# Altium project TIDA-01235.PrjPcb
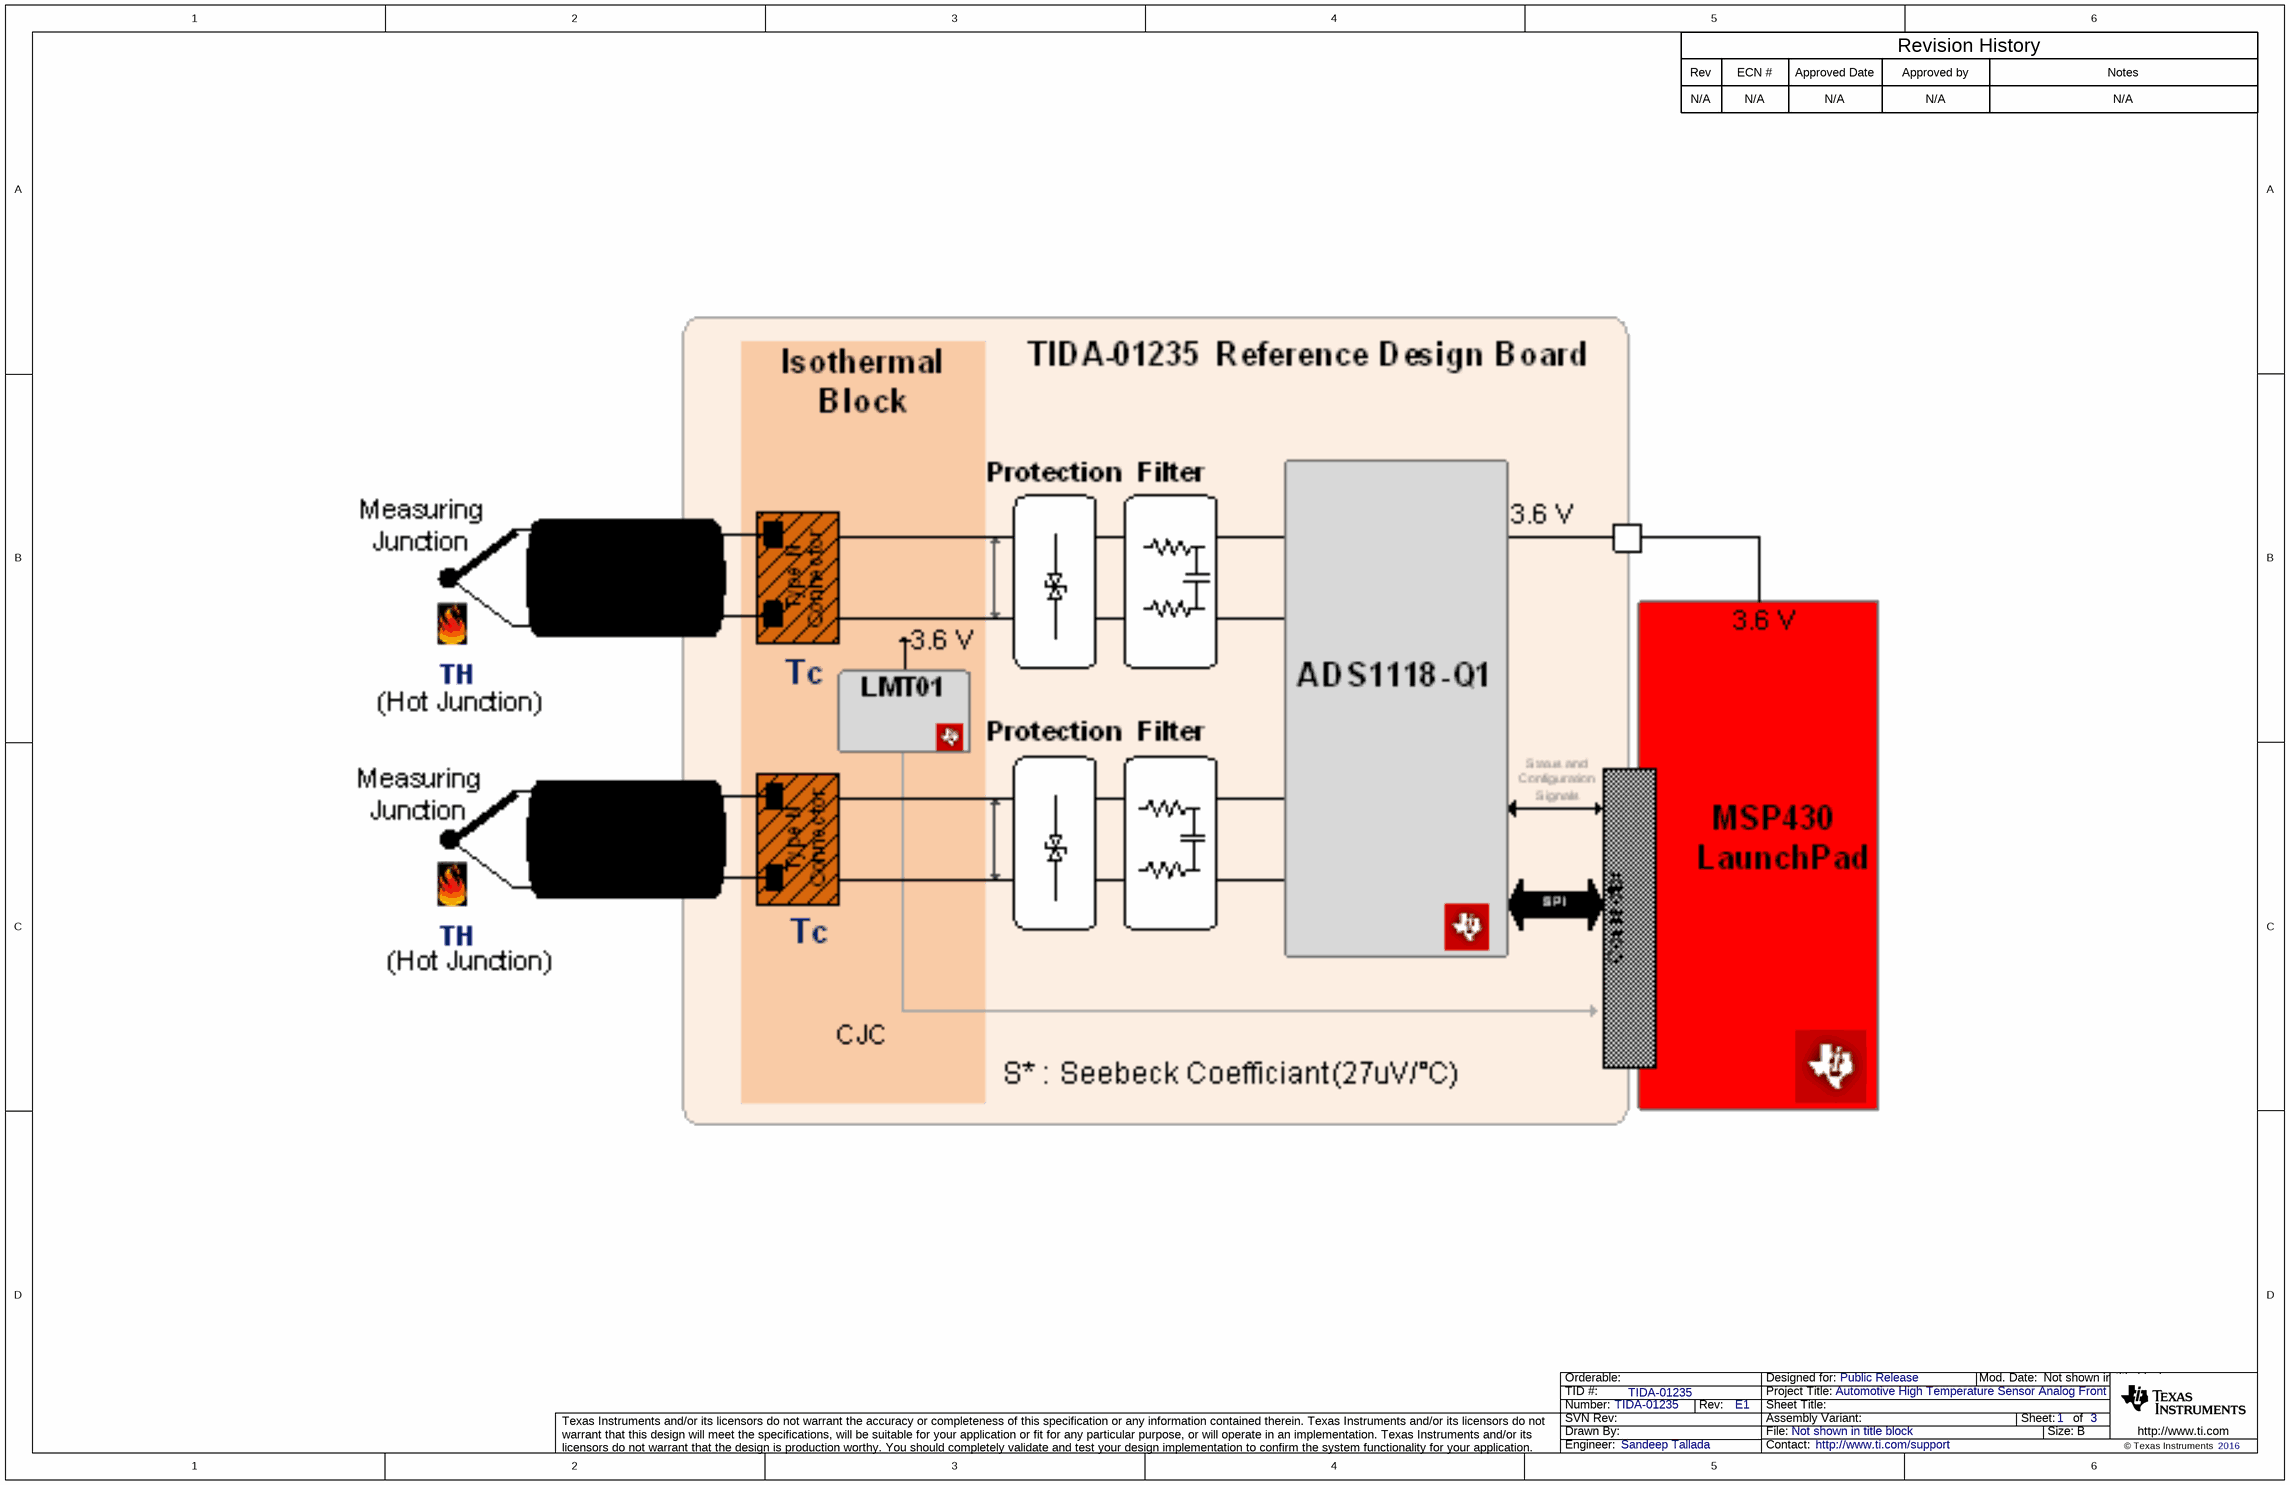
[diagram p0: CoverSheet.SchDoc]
CopyrightYear: 2016; PCB_Layout: Sandeep Tallada; PCB_Rev: E1; PRJ_Customer: Public Release; PRJ_Engineer: Sandeep Tallada; PRJ_Number: TIDA-01235; PRJ_Title: Automotive High Temperature Sensor Analog Front End Reference Design; SCH_Rev: E1; TechSupport: http://www.ti.com/support; TID: TIDA-01235
3 sheets, 60 parts. Net scope: flat (ports and power ports of the same name join across sheets).
Board file: PCB.PcbDoc
Sheets:
  CoverSheet.SchDoc
  BlankSheet.SchDoc
  EVM_Hardware.SchDoc

## Sheet CoverSheet.SchDoc
size 431 x 279 mm; Date: Not shown in title block; ApprovedBy: Not shown in title block; CheckedBy: Not shown in title block; Author: Not shown in title block; CompanyName: Not shown in title block; Engineer: Not shown in title block; Organization: Not shown in title block; Address1: Not shown in title block; Address2: Not shown in title block; Address3: Not shown in title block; Address4: Not shown in title block; DocumentNumber: 1; Revision: Use project parameter SCH_Rev; SheetNumber: 1; SheetTotal: 3; PageSetup: Record=PageOptions¦CenterHorizontal=True¦CenterVertical=True¦PrintScale=1.00¦XCorrection=1.00¦YCorrection=1.00¦PrintKind=0¦BorderSize=5000000¦LeftOffset=0¦BottomOffset=0¦Orientation=2¦PaperLength=1000¦PaperWidth=1000¦Scale=100¦PaperSource=15¦PrintQuality=600¦MediaType=1¦DitherType=10¦PaperKind=Letter¦PrintScaleMode=1

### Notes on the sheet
- Rev
- N/A
- ECN #
- Approved Date
- Approved by
- Revision History
- Notes
- Place Block Diagram here (if appropriate) or delete this text box.
  If using a block diagram from another tool, save the picture as a .bmp file.
  Then, use menu Place|Drawing Tools|Graphic to insert the .png/.svg/.bmp file on the schematic.

## Sheet BlankSheet.SchDoc: Automotive HTS Schematic
size 431 x 279 mm; Date: Not shown in title block; ApprovedBy: Not shown in title block; CheckedBy: Not shown in title block; Author: Not shown in title block; CompanyName: Not shown in title block; DrawnBy: Sandeep Tallada; Engineer: Not shown in title block; Organization: Not shown in title block; Address1: Not shown in title block; Address2: Not shown in title block; Address3: Not shown in title block; Address4: Not shown in title block; DocumentNumber: 1; Revision: Use project parameter SCH_Rev; SheetNumber: 1; SheetTotal: 1; PageSetup: Record=PageOptions¦CenterHorizontal=True¦CenterVertical=True¦PrintScale=1.00¦XCorrection=1.00¦YCorrection=1.00¦PrintKind=0¦BorderSize=5000000¦LeftOffset=0¦BottomOffset=0¦Orientation=2¦PaperLength=1000¦PaperWidth=1000¦Scale=100¦PaperSource=15¦PrintQuality=600¦MediaType=1¦DitherType=10¦PaperKind=Letter¦PrintScaleMode=1
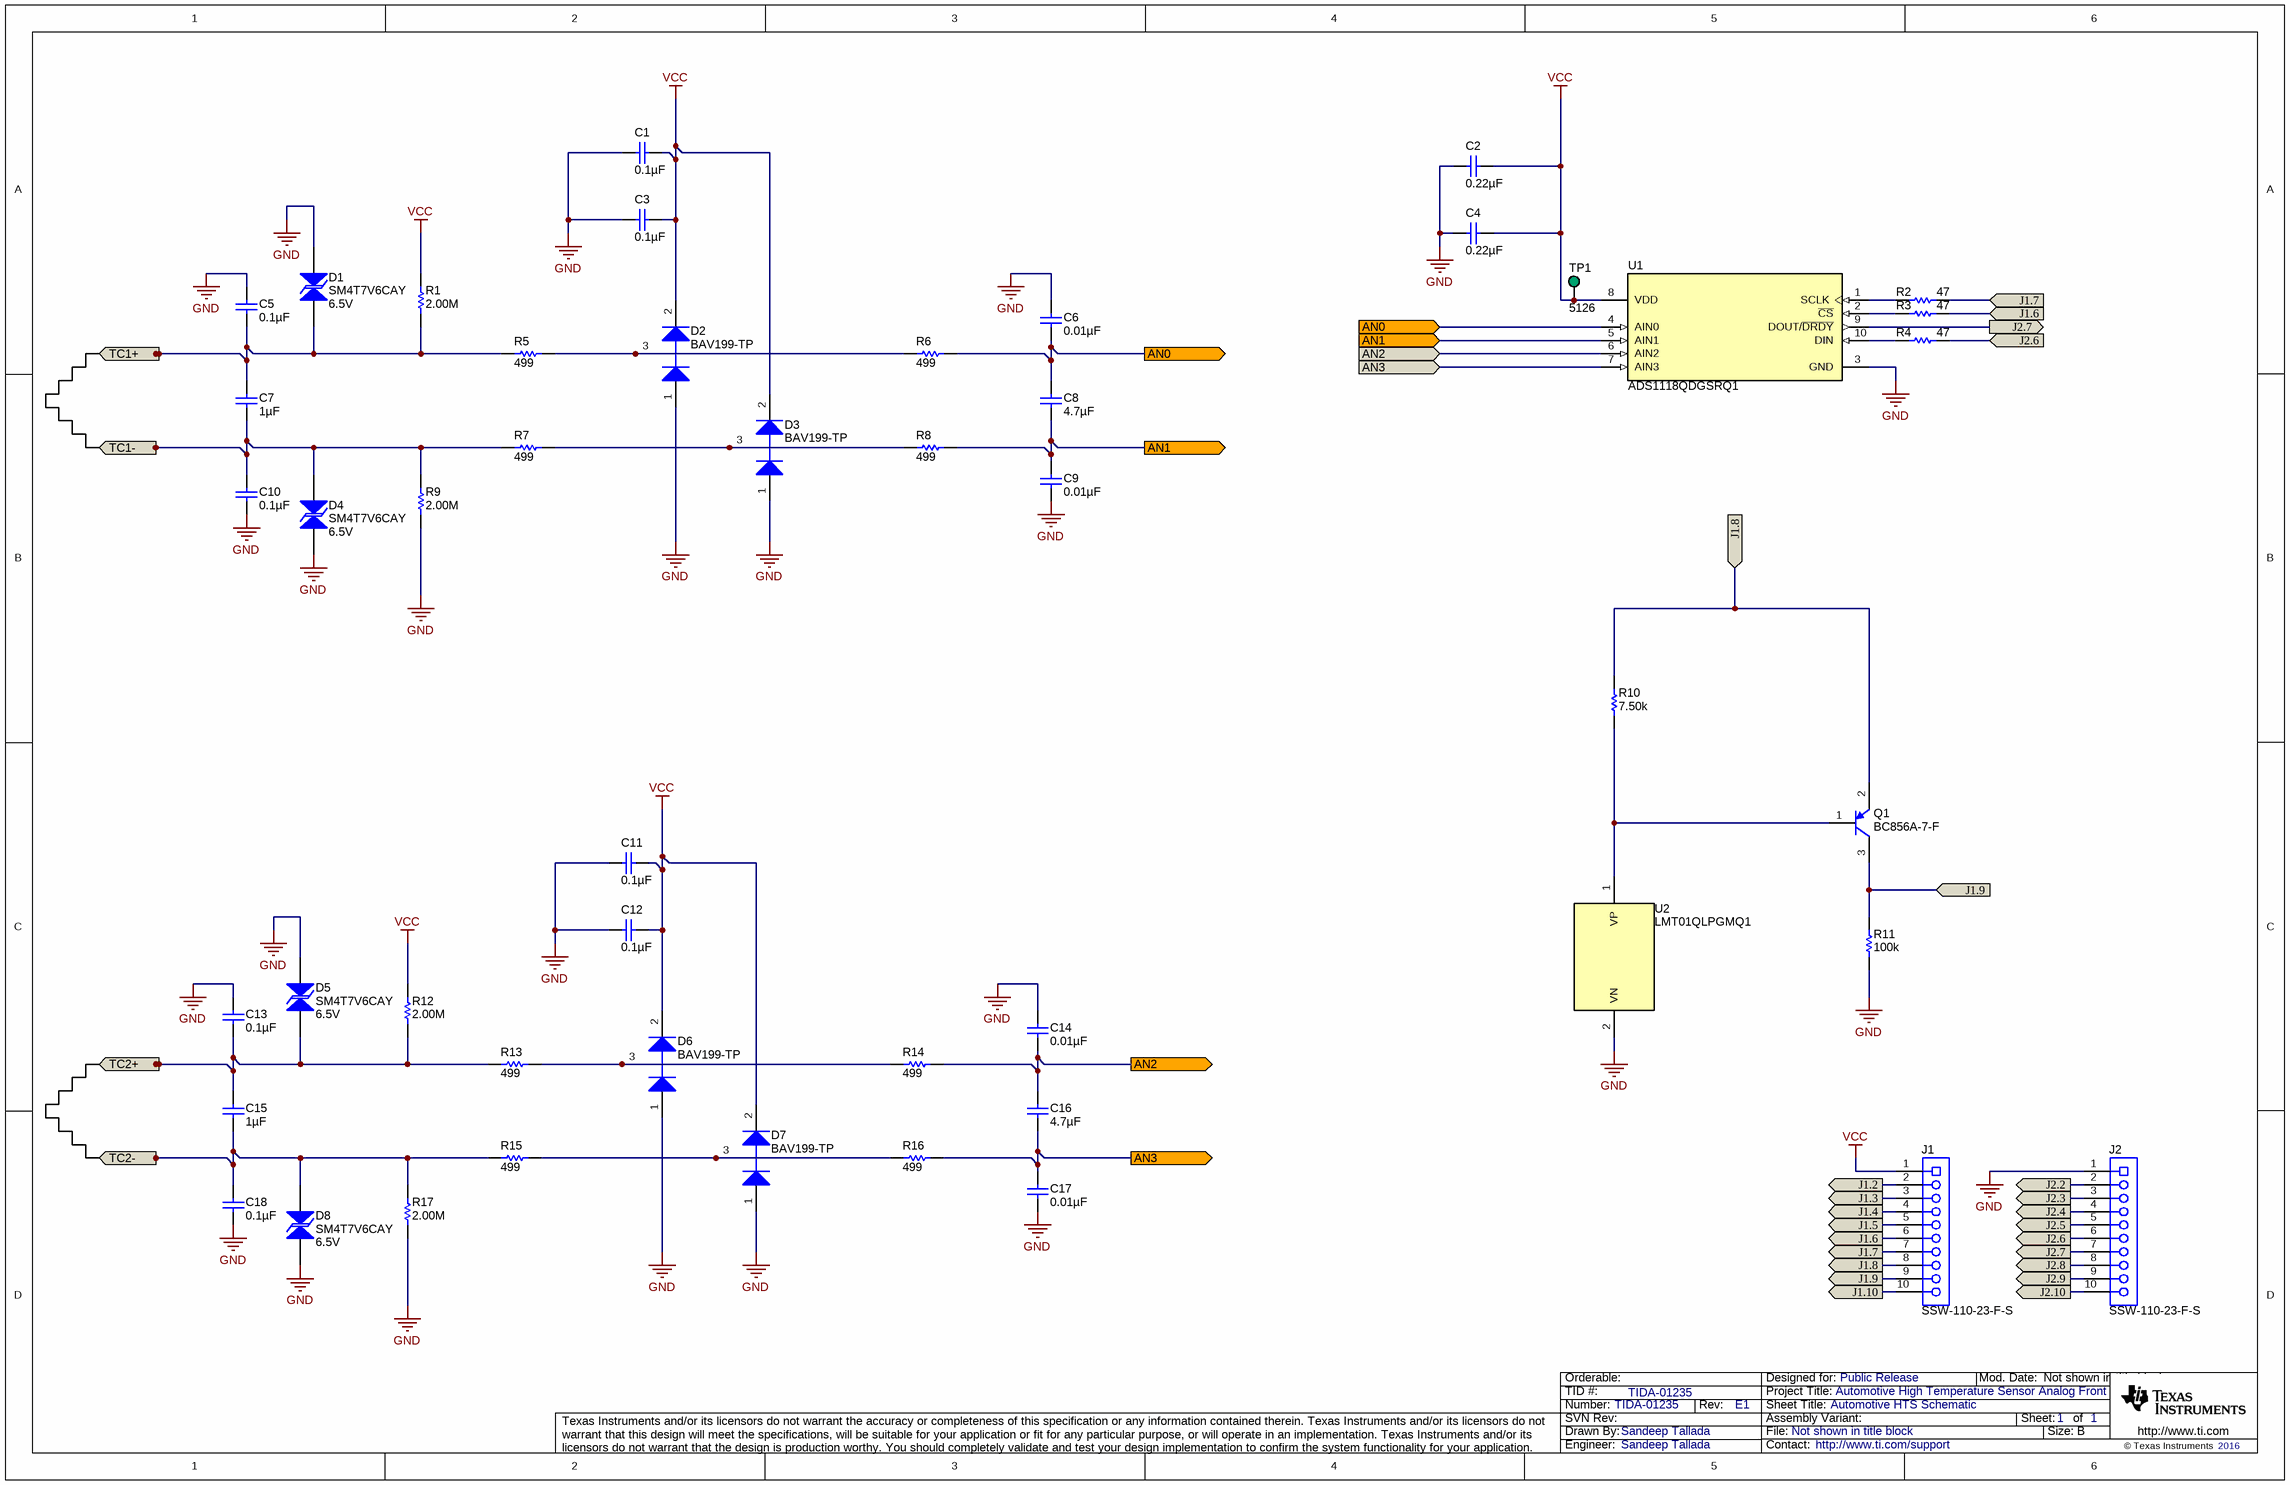
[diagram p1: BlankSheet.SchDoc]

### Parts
C1  ValueDisplayed: 0.1µF  [0805]  (hidden comment: CGA4J2X8R1H104M125AA)
C2  ValueDisplayed: 0.22µF  [0603S]  (hidden comment: CGA3E3X8R1E224K080AB)
C3  ValueDisplayed: 0.1µF  [0805]  (hidden comment: CGA4J2X8R1H104M125AA)
C4  ValueDisplayed: 0.22µF  [0603S]  (hidden comment: CGA3E3X8R1E224K080AB)
C5  ValueDisplayed: 0.1µF  [0805]  (hidden comment: CGA4J2X8R1H104M125AA)
C6  ValueDisplayed: 0.01µF  [0603S]  (hidden comment: C1608NP01H103J080AA)
C7  ValueDisplayed: 1µF  [1206_180]  (hidden comment: CGA5L3X8R1H105K160AB)
C8  ValueDisplayed: 4.7µF  [0603S]  (hidden comment: C0603C475K8PACTU)
C9  ValueDisplayed: 0.01µF  [0603S]  (hidden comment: C1608NP01H103J080AA)
C10  ValueDisplayed: 0.1µF  [0805]  (hidden comment: CGA4J2X8R1H104M125AA)
C11  ValueDisplayed: 0.1µF  [0805_HV]  (hidden comment: CGA4J2X8R1H104M125AA)
C12  ValueDisplayed: 0.1µF  [0805_HV]  (hidden comment: CGA4J2X8R1H104M125AA)
C13  ValueDisplayed: 0.1µF  [0805]  (hidden comment: CGA4J2X8R1H104M125AA)
C14  ValueDisplayed: 0.01µF  [0603S]  (hidden comment: C1608NP01H103J080AA)
C15  ValueDisplayed: 1µF  [1206_180]  (hidden comment: CGA5L3X8R1H105K160AB)
C16  ValueDisplayed: 4.7µF  [0603S]  (hidden comment: C0603C475K8PACTU)
C17  ValueDisplayed: 0.01µF  [0603S]  (hidden comment: C1608NP01H103J080AA)
C18  ValueDisplayed: 0.1µF  [0805]  (hidden comment: CGA4J2X8R1H104M125AA)
D1  SM4T7V6CAY  value 6.5V  [SMA]
D2  BAV199-TP  [SOT-23]
D3  BAV199-TP  [SOT-23]
D4  SM4T7V6CAY  value 6.5V  [SMA]
D5  SM4T7V6CAY  value 6.5V  [SMA]
D6  BAV199-TP  [SOT-23]
D7  BAV199-TP  [SOT-23]
D8  SM4T7V6CAY  value 6.5V  [SMA]
J1  SSW-110-23-F-S  [CONN_SSW-110-23-F-S]
J2  SSW-110-23-F-S  [CONN_SSW-110-23-F-S]
Q1  BC856A-7-F  [SOT-23]
R1  ValueDisplayed: 2.00M  [0402S]  (hidden comment: ERJ-U02F2004X)
R2  ValueDisplayed: 47  [0402S]  (hidden comment: ERJ-2GEJ470X)
R3  ValueDisplayed: 47  [0402S]  (hidden comment: ERJ-2GEJ470X)
R4  ValueDisplayed: 47  [0402S]  (hidden comment: ERJ-2GEJ470X)
R5  ValueDisplayed: 499  [0402S]  (hidden comment: ERA-2AEB4990X)
R6  ValueDisplayed: 499  [0402S]  (hidden comment: ERA-2AEB4990X)
R7  ValueDisplayed: 499  [0402S]  (hidden comment: ERA-2AEB4990X)
R8  ValueDisplayed: 499  [0402S]  (hidden comment: ERA-2AEB4990X)
R9  ValueDisplayed: 2.00M  [0402S]  (hidden comment: ERJ-U02F2004X)
R10  ValueDisplayed: 7.50k  [0402S]  (hidden comment: ERA-2AEB752X)
R11  ValueDisplayed: 100k  [0402S]  (hidden comment: ERJ-2GEJ104X)
R12  ValueDisplayed: 2.00M  [0402S]  (hidden comment: ERJ-U02F2004X)
R13  ValueDisplayed: 499  [0402S]  (hidden comment: ERA-2AEB4990X)
R14  ValueDisplayed: 499  [0402S]  (hidden comment: ERA-2AEB4990X)
R15  ValueDisplayed: 499  [0402S]  (hidden comment: ERA-2AEB4990X)
R16  ValueDisplayed: 499  [0402S]  (hidden comment: ERA-2AEB4990X)
R17  ValueDisplayed: 2.00M  [0402S]  (hidden comment: ERJ-U02F2004X)
TP1  5126  [Keystone5126]
U1  ADS1118QDGSRQ1  [DGS0010A_N]
U2  LMT01QLPGMQ1  [LPG0002A]

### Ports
AN0 (in), AN0 (out), AN1 (in), AN1 (out), AN2 (in), AN2 (out), AN3 (in), AN3 (out), J1.2, J1.3, J1.4, J1.5, J1.6, J1.7, J1.8, J1.9, J1.10, J2.2, J2.3, J2.4, J2.5, J2.6, J2.7, J2.7 (out), J2.8, J2.9, J2.10, TC1+, TC1-, TC2+, TC2-

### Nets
GND: C1.1 C2.2 C3.1 C4.2 C5.1 C6.1 C9.2 C10.2 C11.1 C12.1 C13.1 C14.1 C17.2 C18.2 D1.2 D2.1(A) D3.1(A) D4.1 D5.2 D6.1(A) D7.1(A) D8.1 J2.1 R9.1 R11.1 R17.1 U1.3(GND) U2.2(VN)
VCC: C1.2 C2.1 C3.2 C4.1 C11.2 C12.2 D2.2(K) D3.2(K) D6.2(K) D7.2(K) J1.1 R1.2 R12.2 TP1.1 U1.8(VDD)
AN0: C6.2 C8.1 R6.2 U1.4(AIN0) ; port AN0
AN1: C8.2 C9.1 R8.2 U1.5(AIN1) ; port AN1
AN2: C14.2 C16.1 R14.2 U1.6(AIN2) ; port AN2
AN3: C16.2 C17.1 R16.2 U1.7(AIN3) ; port AN3
J1.2: J1.2 ; port J1.2
J1.3: J1.3 ; port J1.3
J1.4: J1.4 ; port J1.4
J1.5: J1.5 ; port J1.5
J1.6: J1.6 R3.2 ; port J1.6
J1.7: J1.7 R2.2 ; port J1.7
J1.8: J1.8 Q1.2(E) R10.2 ; port J1.8
J1.9: J1.9 Q1.3(C) R11.2 ; port J1.9
J1.10: J1.10 ; port J1.10
J2.2: J2.2 ; port J2.2
J2.3: J2.3 ; port J2.3
J2.4: J2.4 ; port J2.4
J2.5: J2.5 ; port J2.5
J2.6: J2.6 R4.2 ; port J2.6
J2.7: J2.7 U1.9(DOUT/~{DRDY}) ; port J2.7
J2.8: J2.8 ; port J2.8
J2.9: J2.9 ; port J2.9
J2.10: J2.10 ; port J2.10
TC1+: C5.2 C7.1 D1.1 R1.1 R5.1 ; port TC1+
TC1-: C7.2 C10.1 D4.2 R7.1 R9.2 ; port TC1-
TC2+: C13.2 C15.1 D5.1 R12.1 R13.1 ; port TC2+
TC2-: C15.2 C18.1 D8.2 R15.1 R17.2 ; port TC2-
NetD2_3: D2.3(C) R5.2 R6.1
NetD3_3: D3.3(C) R7.2 R8.1
NetD6_3: D6.3(C) R13.2 R14.1
NetD7_3: D7.3(C) R15.2 R16.1
NetQ1_1: Q1.1(B) R10.1 U2.1(VP)
NetR2_1: R2.1 U1.1(SCLK)
NetR3_1: R3.1 U1.2(~{CS})
NetR4_1: R4.1 U1.10(DIN)

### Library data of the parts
C1 C3 C5 C10 C13 C18 = CGA4J2X8R1H104M125AA: CAP, CERM, 0.1 µF, 50 V, +/- 20%, X8R, AEC-Q200 Grade 0, 0805; Manufacturer: TDK; Polarized: N; CompType: Capacitor; Value: 0.1uF; U/M: EA; Cap_F: 0.0000001; Tolerance_%: 20; Value1: Unknown; VDC_V: 50; Value2: 50V; TaMin_C: -55; TaMax_C: 150; SizeArea_mm2: 2.5; SizeAreaWB_mm2: 6.75; SizeX_mm: 2; SizeY_mm: 1.25; SizeZ_mm: 1.45; AEC Category: Q200; AEC Qualified: Y; AEC Grade: 0
C2 C4 = CGA3E3X8R1E224K080AB: CAP, CERM, 0.22 µF, 25 V, +/- 10%, X8R, AEC-Q200 Grade 0, 0603; Manufacturer: TDK; Polarized: N; CompType: Capacitor; Value: 0.22uF; U/M: EA; Cap_F: 0.00000022; Tolerance_%: 10; Value1: Unknown; VDC_V: 25; Value2: 25V; TaMin_C: -55; TaMax_C: 150; Cap_Case: 0603; SizeArea_mm2: 1.28; SizeAreaWB_mm2: 4.68; SizeX_mm: 1.6; SizeY_mm: 0.8; SizeZ_mm: 1; AEC Category: Q200; AEC Qualified: Y; AEC Grade: 0
C6 C9 C14 C17 = C1608NP01H103J080AA: CAP, CERM, 0.01 µF, 50 V, +/- 5%, C0G/NP0, 0603; Manufacturer: TDK; Polarized: N; CompType: Capacitor; Value: 0.01uF; U/M: EA; Cap_F: 0.00000001; Tolerance_%: 5; Value1: Unknown; VDC_V: 50; Value2: 50V; TaMin_C: -55; TaMax_C: 150; Cap_Case: 0603; SizeArea_mm2: 1.28; SizeAreaWB_mm2: 4.68; SizeX_mm: 1.6; SizeY_mm: 0.8; SizeZ_mm: 1; AEC Category: Q200
C7 C15 = CGA5L3X8R1H105K160AB: CAP, CERM, 1 µF, 50 V, +/- 10%, X8R, AEC-Q200 Grade 0, 1206; Manufacturer: TDK; Polarized: N; CompType: Capacitor; Value: 1uF; U/M: EA; Cap_F: 0.000001; Tolerance_%: 10; Value1: Unknown; VDC_V: 50; Value2: 50V; TaMin_C: -55; TaMax_C: 150; Cap_Case: 1206; SizeArea_mm2: 5.12; SizeAreaWB_mm2: 10.92; SizeX_mm: 3.2; SizeY_mm: 1.6; SizeZ_mm: 1.8; AEC Category: Q200; AEC Qualified: Y; AEC Grade: 0
C8 C16 = C0603C475K8PACTU: CAP, CERM, 4.7 µF, 10 V, +/- 10%, X5R, 0603; Manufacturer: Kemet; Polarized: N; CompType: Capacitor; Value: 4.7uF; U/M: EA; Cap_F: 0.0000047; Tolerance_%: 10; ESR_ohm: 0.006; Value1: 0.006 ohm; Value2: 10V; IRMS_A: 7.24; TaMin_C: -55; TaMax_C: 85; Cap_Case: 0603; SizeArea_mm2: 1.28; SizeAreaWB_mm2: 4.68; SizeX_mm: 1.6; SizeY_mm: 0.8; SizeZ_mm: 1; AEC Category: Q200
C11 C12 = CGA4J2X8R1H104M125AA: CAP, CERM, 0.1 µF, 50 V, +/- 20%, X8R, AEC-Q200 Grade 0, 0805; Manufacturer: TDK; Polarized: N; CompType: Capacitor; Value: 0.1uF; U/M: EA; Cap_F: 0.0000001; Tolerance_%: 20; Value1: Unknown; VDC_V: 50; Value2: 50V; TaMin_C: -55; TaMax_C: 150; Cap_Case: 0805; SizeArea_mm2: 2.5; SizeAreaWB_mm2: 6.75; SizeX_mm: 2; SizeY_mm: 1.25; SizeZ_mm: 1.45; AEC Category: Q200; AEC Qualified: Y; AEC Grade: 0
D1 D4 D5 D8 = SM4T7V6CAY: Diode, TVS, Bi, 6.5 V, 400 W, AEC-Q101, SMA; Manufacturer: STMicroelectronics; U/M: EA; Power_W: 400; Vr_V: 6.5; Value1: 400W; SizeAreaWB_mm2: 37.3428; SizeArea_mm2: 16.3228; SizeX_mm: 5.59; SizeY_mm: 2.92; SizeZ_mm: 2.87; AEC Category: Q101; AEC Qualified: Y
D2 D3 D6 D7 = BAV199-TP: Diode, Switching, 70 V, 0.215 A, SOT-23; Manufacturer: Micro Commercial Components; U/M: EA; Value: 70V; Value1: 0.215A; Io_A: 0.215; Vr_V: 70; TJmax_C: 150; SizeAreaWB_mm2: 14; SizeArea_mm2: 7.5; SizeX_mm: 2.5; SizeY_mm: 3; SizeZ_mm: 1.1; AEC Category: Q101
J1 J2 = SSW-110-23-F-S: Connector, Receptacle, 100mil, 10x1, Gold plated, TH; Manufacturer: Samtec; SymbolCreator: a0411947
Q1 = BC856A-7-F, Diodes Inc.: Transistor, PNP, 65 V, 0.01 A, SOT-23; CompType: BJT; PNP: 1; NPN: 0; Vceo_V: 65; Vcesat1_V: 0.3; Value: 65 V; IcRated_A: 0.01; Value1: 0.01 A; TaMin_C: -65; TaMax_C: 150; U/M: EA; AEC Category: Q101
R1 R9 R12 R17 = ERJ-U02F2004X: RES, 2.00 M, 1%, 0.1 W, AEC-Q200 Grade 0, 0402; Manufacturer: Panasonic; CompType: Resistor; Value: 2.00Meg; Res_ohm: 2000000; Value_Code: 2M00; Tolerance_%: 1; Power_W: 0.1; Value2: 0.1W; VDC_V: 50; TempCo: 400 ppm/C; SizeArea_mm2: 0.5; SizeZ_mm: 0.6; EIA_Code: E96; U/M: EA; AEC Category: Q200; AEC Qualified: Y; AEC Grade: 0
R2-R4 = ERJ-2GEJ470X: RES, 47, 5%, 0.1 W, AEC-Q200 Grade 0, 0402; Manufacturer: Panasonic; CompType: Resistor; Value: 47; Value_Code: 47R0; Tolerance_%: 5; Power_W: 0.1; Value2: 0.1W; TempCo: 200 ppm/C; SizeArea_mm2: 0.5; SizeX_mm: 1; SizeZ_mm: 0.6; EIA_Code: E24; U/M: EA; AEC Category: Q200; AEC Qualified: Y; AEC Grade: 0
R5-R8 R13-R16 = ERA-2AEB4990X: RES, 499, 0.1%, 0.063 W, AEC-Q200 Grade 0, 0402; Manufacturer: Panasonic; CompType: Resistor; Value: 499; Value_Code: 499R; Tolerance_%: 0.1; Power_W: 0.063; Value2: 0.063W; VDC_V: 50; TempCo: 25 ppm/C; SizeArea_mm2: 0.5; SizeX_mm: 1; SizeZ_mm: 0.6; EIA_Code: E192; U/M: EA; AEC Category: Q200; AEC Qualified: Y; AEC Grade: 0
R10 = ERA-2AEB752X: RES, 7.50 k, 0.1%, 0.063 W, AEC-Q200 Grade 0, 0402; Manufacturer: Panasonic; CompType: Resistor; Value: 7.50k; Res_ohm: 7500; Value_Code: 7k50; Tolerance_%: 0.1; Power_W: 0.063; Value2: 0.063W; VDC_V: 50; TempCo: 25 ppm/C; SizeArea_mm2: 0.5; SizeX_mm: 1; SizeZ_mm: 0.6; EIA_Code: E192; U/M: EA; AEC Category: Q200; AEC Qualified: Y; AEC Grade: 0
R11 = ERJ-2GEJ104X: RES, 100 k, 5%, 0.1 W, AEC-Q200 Grade 0, 0402; Manufacturer: Panasonic; CompType: Resistor; Value: 100k; Res_ohm: 100000; Tolerance_%: 5; Power_W: 0.1; Value2: 0.1W; VDC_V: 50; TempCo: 200 ppm/C; SizeArea_mm2: 0.5; SizeX_mm: 1; SizeZ_mm: 0.6; EIA_Code: E24; U/M: EA; AEC Category: Q200; AEC Qualified: Y; AEC Grade: 0
TP1 = 5126: Test Point, Multipurpose, Green, TH; Manufacturer: Keystone; SymbolCreator: a0412235; CompType: Test Point Loop; ContactFinish: Silver
U1 = ADS1118QDGSRQ1: Low-Power, SPI-Compatible, 16-Bit Analog-to-Digital Converter With Internal Reference and Temperature Sensor, DGS0010A; Manufacturer: Texas Instruments; SymbolCreator: Altium; SizeArea_mm2: 14.7; SizeAreaWB_mm2: 23.6; SizeX_mm: 4.9; SizeY_mm: 3; SizeZ_mm: 1.1; CompType: IC; U/M: EA
U2 = LMT01QLPGMQ1: 0.5°C Accurate 2-Pin Digital Output Temperature Sensor with Pulse Count Interface, LPG0002A (TO-92-2); Alternate PartNumber: LMT01QLPGQ1; Manufacturer: Texas Instruments; SymbolCreator: Altium; SizeArea_mm2: 12.6; SizeAreaWB_mm2: 20.75; SizeX_mm: 4; SizeY_mm: 3.15; SizeZ_mm: 5.05; CompType: IC; U/M: EA

## Sheet EVM_Hardware.SchDoc
size 431 x 279 mm; Date: Not shown in title block; ApprovedBy: Not shown in title block; CheckedBy: Not shown in title block; Author: Not shown in title block; CompanyName: Not shown in title block; Engineer: Not shown in title block; Organization: Not shown in title block; Address1: Not shown in title block; Address2: Not shown in title block; Address3: Not shown in title block; Address4: Not shown in title block; DocumentNumber: 1; Revision: Use project parameter SCH_Rev; SheetNumber: 3; SheetTotal: 3; PageSetup: Record=PageOptions¦CenterHorizontal=True¦CenterVertical=True¦PrintScale=1.00¦XCorrection=1.00¦YCorrection=1.00¦PrintKind=0¦BorderSize=5000000¦LeftOffset=0¦BottomOffset=0¦Orientation=2¦PaperLength=1000¦PaperWidth=1000¦Scale=100¦PaperSource=15¦PrintQuality=600¦MediaType=1¦DitherType=10¦PaperKind=Letter¦PrintScaleMode=1
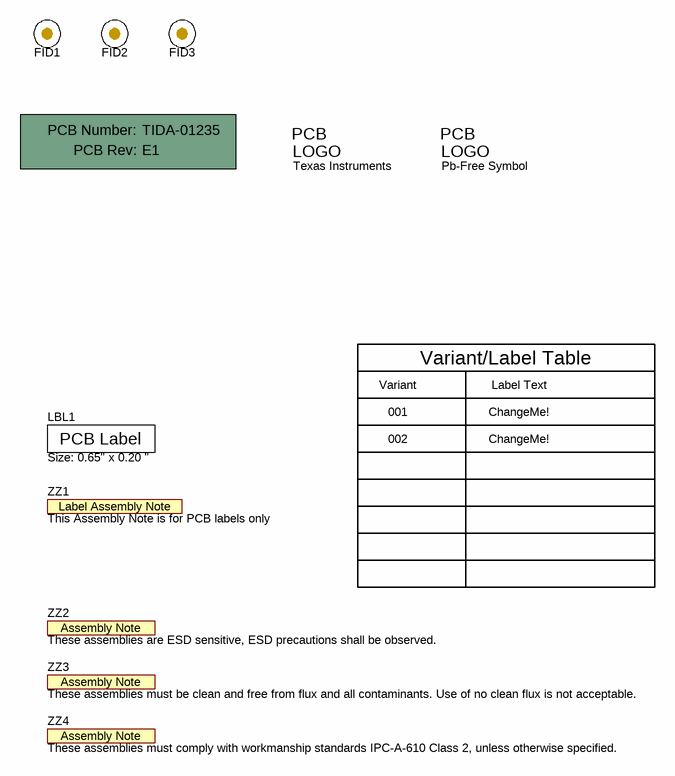
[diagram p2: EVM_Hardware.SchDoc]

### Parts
!PCB1  Printed Circuit Board  (value not drawn)  (mechanical)
FID1  Fiducial  [Fiducial10-20]  (value not drawn)
FID2  Fiducial  [Fiducial10-20]  (value not drawn)
FID3  Fiducial  [Fiducial10-20]  (value not drawn)
LBL1  Size: 0.65" x 0.20 "  [Label_650x200]
Logo1  Texas Instruments  [TI_Stacked_SolderMask_Small]  (no BOM)
Logo2  Pb-Free Symbol  [Pb-Free_Overlay_Small]  (no BOM)
ZZ1  This Assembly Note is for PCB labels only  [AssemblyNoteLabel]  (no BOM)
ZZ2  These assemblies are ESD sensitive, ESD precautions shall be observed.  [AssemblyNote]  (no BOM)
ZZ3  These assemblies must be clean and free from flux and all contaminants. Use of no clean flux is not acceptable.  [AssemblyNote]  (no BOM)
ZZ4  These assemblies must comply with workmanship standards IPC-A-610 Class 2, unless otherwise specified.  [AssemblyNote]  (no BOM)

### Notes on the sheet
- Variant
- Variant/Label Table
- Label Text
- 001
- 002
- ChangeMe!

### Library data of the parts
!PCB1 = PCB: Manufacturer: Any; PartNumber: TIDA-01235; SymbolCreator: a0412235
FID1-FID3 = Fiducial: Fiducial mark.  There is nothing to buy or mount.; SymbolCreator: codlsc
LBL1 = THT-14-423-10: Thermal Transfer Printable Labels, 0.650" W x 0.200" H - 10,000 per roll; Manufacturer: Brady; SymbolCreator: a0412235; CompType: Label
Logo1 = TI_Logo: Texas Instrument Corporate Signature; SymbolCreator: codlsc
Logo2 = Pb-Free: SymbolCreator: a0412235
ZZ1 = AssemblyNoteLabel: SymbolCreator: a0412235
ZZ2-ZZ4 = AssemblyNote: SymbolCreator: codlsc

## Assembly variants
001: not fitted FID1 FID2 FID3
